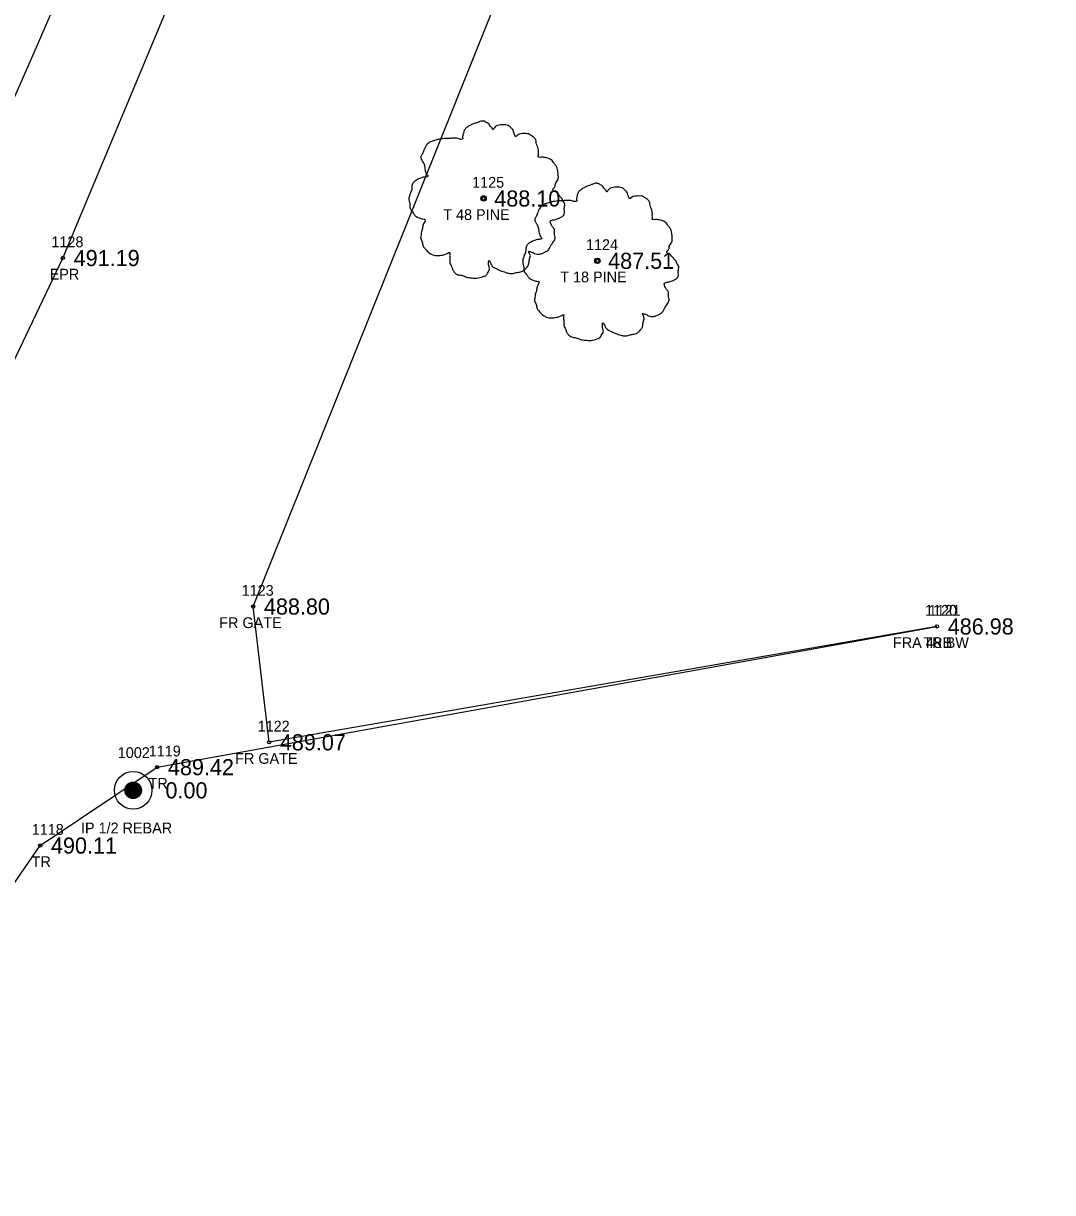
# Model space of a CAD drawing. Extents: x 1649047 to 1650429, y 896228 to 898747.
# Drawn here: x 1649848.7 to 1649944.4, y 897230.6 to 897339.2 of the extents above; entities that cross this region are included whole.
import ezdxf

# ---------------------------------------------------------------- set-up
doc = ezdxf.new("R2010")
doc.units = 0
for name, color, linetype in [('RD_EX_DV_Prop_txCode', 7, 'Continuous'), ('RD_EX_DV_PropPin', 7, 'Continuous'), ('RD_EX_Fence_Other', 7, 'Continuous'), ('RD_EX_Fence_Other_txCode', 7, 'Continuous'), ('RD_EX_Road', 7, 'Continuous'), ('RD_EX_Road_txCode', 7, 'Continuous'), ('RD_EX_TX_DV_Prop_ELEV', 7, 'Continuous'), ('RD_EX_TX_Fence_Other_ELEV', 7, 'Continuous'), ('RD_EX_TX_Road_ELEV', 7, 'Continuous'), ('RD_EX_TX_VEG_ELEV', 7, 'Continuous'), ('RD_EX_VEG', 7, 'Continuous'), ('RD_EX_VEG_txCode', 7, 'Continuous'), ('RD_HC_Cl', 7, 'Continuous'), ('RD_SMD_Locator', 7, 'Continuous')]:
    doc.layers.add(name, color=color, linetype=linetype)

msp = doc.modelspace()

# ---------------------------------------------------------------- linework, layer by layer
at = {"layer": 'RD_EX_DV_PropPin'}
for p, q in [((1649858.22, 897267.7), (1649858.22, 897268.29)), ((1649858.25, 897267.62), (1649858.25, 897268.36)), ((1649858.29, 897267.57), (1649858.29, 897268.42)), ((1649858.32, 897267.52), (1649858.32, 897268.47)), ((1649858.36, 897267.48), (1649858.36, 897268.51)), ((1649858.39, 897267.44), (1649858.39, 897268.54)), ((1649858.43, 897267.41), (1649858.43, 897268.58)), ((1649858.46, 897267.38), (1649858.46, 897268.6)), ((1649858.5, 897267.36), (1649858.5, 897268.63)), ((1649858.53, 897267.34), (1649858.53, 897268.65)), ((1649858.57, 897267.32), (1649858.57, 897268.67)), ((1649858.6, 897267.3), (1649858.6, 897268.69)), ((1649858.64, 897267.29), (1649858.64, 897268.7)), ((1649858.67, 897267.27), (1649858.67, 897268.71)), ((1649858.71, 897267.26), (1649858.71, 897268.72)), ((1649858.74, 897267.25), (1649858.74, 897268.73)), ((1649858.78, 897267.25), (1649858.78, 897268.74)), ((1649858.81, 897267.24), (1649858.81, 897268.75)), ((1649858.85, 897267.24), (1649858.85, 897268.75)), ((1649858.88, 897267.23), (1649858.88, 897268.75)), ((1649858.92, 897267.23), (1649858.92, 897268.75)), ((1649858.95, 897267.23), (1649858.95, 897268.75)), ((1649858.99, 897267.24), (1649858.99, 897268.75)), ((1649859.02, 897267.24), (1649859.02, 897268.75)), ((1649859.06, 897267.25), (1649859.06, 897268.74)), ((1649859.09, 897267.25), (1649859.09, 897268.73)), ((1649859.13, 897267.26), (1649859.13, 897268.72)), ((1649859.16, 897267.27), (1649859.16, 897268.71)), ((1649859.2, 897267.29), (1649859.2, 897268.7)), ((1649859.23, 897267.3), (1649859.23, 897268.69)), ((1649859.27, 897267.32), (1649859.27, 897268.67)), ((1649859.3, 897267.34), (1649859.3, 897268.65)), ((1649859.34, 897267.36), (1649859.34, 897268.63)), ((1649859.37, 897267.38), (1649859.37, 897268.6)), ((1649859.41, 897267.41), (1649859.41, 897268.58)), ((1649859.44, 897267.44), (1649859.44, 897268.54)), ((1649859.48, 897267.48), (1649859.48, 897268.51)), ((1649859.51, 897267.52), (1649859.51, 897268.47)), ((1649859.55, 897267.57), (1649859.55, 897268.42)), ((1649859.58, 897267.62), (1649859.58, 897268.36)), ((1649859.62, 897267.7), (1649859.62, 897268.29)), ((1649858.18, 897267.8), (1649858.18, 897268.19)), ((1649859.65, 897267.8), (1649859.65, 897268.19))]:
    msp.add_line(p, q, dxfattribs=at)
for radius in [1.75, 0.761]:
    msp.add_circle((1649858.92, 897267.99), radius, dxfattribs=at)
at = {"layer": 'RD_EX_Fence_Other'}
msp.add_lwpolyline([(1649933.62, 897283.21), (1649871.55, 897272.45), (1649870.07, 897285.06), (1649898.31, 897355.41), (1649920.55, 897411.26), (1649908.3, 897415.25)], dxfattribs=at)
at = {"layer": 'RD_EX_Road'}
msp.add_lwpolyline([(1649474.75, 896792.65), (1649502.78, 896827.35), (1649565.2, 896903.92), (1649598.28, 896943.71), (1649629.8, 896982.26), (1649667.92, 897029.33), (1649693.13, 897061.44), (1649723.58, 897101.84), (1649752.37, 897141.09), (1649779.72, 897182.3), (1649806.12, 897225.84), (1649830.13, 897270.79), (1649852.39, 897317.43), (1649871.98, 897364.35), (1649886.55, 897406.09)], dxfattribs=at)
at = {"layer": 'RD_EX_VEG'}
msp.add_lwpolyline([(1649692.17, 896958.45), (1649681.22, 896988.83), (1649682.34, 897025.02), (1649740.01, 897089.71), (1649819.17, 897217.64), (1649850.28, 897262.86), (1649861.15, 897270.14), (1649933.62, 897283.21)], dxfattribs=at)
for centre, radius in [((1649891.48, 897322.96), 0.25), ((1649891.47, 897322.94), 0.0001), ((1649902.06, 897317.17), 0.25), ((1649902.05, 897317.15), 0.0001)]:
    msp.add_circle(centre, radius, dxfattribs=at)
for points in [[(1649891.61, 897330.13), (1649891.31, 897330.15), (1649890.99, 897330.05), (1649890.74, 897329.95), (1649890.51, 897329.88), (1649890.29, 897329.78), (1649889.99, 897329.6), (1649889.76, 897329.4), (1649889.64, 897329.15), (1649889.59, 897328.93), (1649889.54, 897328.65), (1649889.54, 897328.48), (1649889.41, 897328.45), (1649889.26, 897328.48), (1649889.01, 897328.55), (1649888.76, 897328.55), (1649888.51, 897328.55), (1649888.16, 897328.53), (1649887.81, 897328.53), (1649887.54, 897328.48), (1649887.21, 897328.43), (1649886.84, 897328.3), (1649886.49, 897328.18), (1649886.19, 897327.93), (1649885.94, 897327.45), (1649885.81, 897327.1), (1649885.66, 897326.85), (1649885.81, 897326.4), (1649885.99, 897326.05), (1649886.01, 897325.85), (1649886.09, 897325.43), (1649886.19, 897325.2), (1649886.31, 897325), (1649886.24, 897324.98), (1649885.86, 897324.93), (1649885.56, 897324.83), (1649885.14, 897324.6), (1649884.91, 897324.38), (1649884.81, 897324.05), (1649884.79, 897323.7), (1649884.69, 897323.5), (1649884.61, 897323.23), (1649884.59, 897323.15), (1649884.54, 897322.83), (1649884.64, 897322.38), (1649884.66, 897322.03), (1649884.79, 897321.81), (1649884.94, 897321.63), (1649885.11, 897321.38), (1649885.51, 897321.16), (1649885.84, 897321.06), (1649886.04, 897321.03), (1649885.86, 897320.53), (1649885.81, 897320.18), (1649885.69, 897319.78), (1649885.69, 897319.71), (1649885.64, 897319.23), (1649885.79, 897318.91), (1649885.86, 897318.53), (1649886.04, 897318.31), (1649886.31, 897318.01), (1649886.64, 897317.78), (1649887.14, 897317.66), (1649887.54, 897317.68), (1649888.11, 897317.86), (1649888.36, 897317.93), (1649888.34, 897317.76), (1649888.36, 897317.38), (1649888.36, 897316.96), (1649888.51, 897316.63), (1649888.61, 897316.36), (1649888.76, 897316.11), (1649889.09, 897315.88), (1649889.49, 897315.81), (1649889.91, 897315.66), (1649890.36, 897315.58), (1649890.86, 897315.56), (1649891.46, 897315.71), (1649891.74, 897315.83), (1649891.84, 897316.01), (1649892.04, 897316.38), (1649891.99, 897316.61), (1649892.01, 897317.21), (1649892.11, 897317.03), (1649892.29, 897316.68), (1649892.78, 897316.38), (1649893.18, 897316.21), (1649893.66, 897316.06), (1649893.96, 897315.98), (1649894.43, 897316.06), (1649894.81, 897316.13), (1649895.18, 897316.26), (1649895.48, 897316.53), (1649895.66, 897316.81), (1649895.71, 897317.08), (1649895.78, 897317.46), (1649895.83, 897317.63)], [(1649895.83, 897317.63), (1649895.76, 897317.81), (1649895.71, 897318.06), (1649895.78, 897318.03), (1649895.96, 897317.98), (1649896.23, 897317.86), (1649896.46, 897317.78), (1649896.78, 897317.81), (1649897.06, 897317.91), (1649897.51, 897318.18), (1649897.78, 897318.66), (1649898.06, 897319.06), (1649898.13, 897319.38), (1649898.08, 897319.61), (1649898.06, 897320.11), (1649897.86, 897320.36), (1649897.81, 897320.48), (1649897.71, 897320.88), (1649897.78, 897320.93), (1649898.06, 897320.98), (1649898.43, 897321.11), (1649898.71, 897321.23), (1649898.93, 897321.41), (1649899.01, 897321.63), (1649898.98, 897322.03), (1649899.03, 897322.43), (1649898.96, 897322.58), (1649898.86, 897322.73), (1649898.78, 897322.93), (1649898.63, 897323.08), (1649898.53, 897323.23), (1649898.43, 897323.33), (1649898.31, 897323.48), (1649898.13, 897323.6), (1649897.98, 897323.65), (1649897.93, 897323.8), (1649898.08, 897324), (1649898.13, 897324.1), (1649898.16, 897324.33), (1649898.38, 897324.68), (1649898.43, 897325.08), (1649898.38, 897325.5), (1649898.33, 897325.78), (1649898.18, 897326.05), (1649897.98, 897326.3), (1649897.86, 897326.48), (1649897.68, 897326.6), (1649897.36, 897326.73), (1649897.11, 897326.78), (1649896.76, 897326.78), (1649896.56, 897326.83), (1649896.58, 897326.88), (1649896.58, 897327.03), (1649896.58, 897327.3), (1649896.51, 897327.75), (1649896.36, 897328.25), (1649896.36, 897328.28), (1649896.26, 897328.53), (1649896.03, 897328.73), (1649895.86, 897328.83), (1649895.66, 897328.95), (1649895.41, 897328.98), (1649895.11, 897328.98), (1649894.83, 897328.93), (1649894.63, 897328.83), (1649894.46, 897328.7), (1649894.38, 897328.85), (1649894.28, 897329.15), (1649894.23, 897329.3), (1649894.08, 897329.48), (1649893.86, 897329.68), (1649893.41, 897329.8), (1649892.78, 897329.73), (1649892.49, 897329.53), (1649892.34, 897329.35), (1649892.29, 897329.48), (1649892.09, 897329.68), (1649891.99, 897329.85), (1649891.81, 897329.98), (1649891.66, 897330.08), (1649891.56, 897330.13)], [(1649902.2, 897324.34), (1649901.9, 897324.37), (1649901.57, 897324.27), (1649901.32, 897324.17), (1649901.1, 897324.09), (1649900.87, 897323.99), (1649900.57, 897323.82), (1649900.35, 897323.62), (1649900.22, 897323.37), (1649900.17, 897323.14), (1649900.12, 897322.87), (1649900.12, 897322.69), (1649900, 897322.67), (1649899.85, 897322.69), (1649899.6, 897322.77), (1649899.35, 897322.77), (1649899.1, 897322.77), (1649898.75, 897322.74), (1649898.4, 897322.74), (1649898.12, 897322.69), (1649897.8, 897322.64), (1649897.42, 897322.52), (1649897.07, 897322.39), (1649896.77, 897322.14), (1649896.52, 897321.67), (1649896.4, 897321.32), (1649896.25, 897321.07), (1649896.4, 897320.62), (1649896.57, 897320.27), (1649896.6, 897320.07), (1649896.67, 897319.64), (1649896.77, 897319.42), (1649896.9, 897319.22), (1649896.82, 897319.19), (1649896.45, 897319.14), (1649896.15, 897319.04), (1649895.72, 897318.82), (1649895.5, 897318.59), (1649895.4, 897318.27), (1649895.37, 897317.92), (1649895.27, 897317.72), (1649895.2, 897317.44), (1649895.17, 897317.37), (1649895.12, 897317.04), (1649895.22, 897316.59), (1649895.25, 897316.24), (1649895.37, 897316.02), (1649895.52, 897315.84), (1649895.7, 897315.59), (1649896.1, 897315.37), (1649896.42, 897315.27), (1649896.62, 897315.24), (1649896.45, 897314.74), (1649896.4, 897314.4), (1649896.27, 897314), (1649896.27, 897313.92), (1649896.22, 897313.45), (1649896.37, 897313.12), (1649896.45, 897312.75), (1649896.62, 897312.52), (1649896.9, 897312.22), (1649897.22, 897312), (1649897.72, 897311.87), (1649898.12, 897311.9), (1649898.7, 897312.07), (1649898.95, 897312.15), (1649898.92, 897311.97), (1649898.95, 897311.6), (1649898.95, 897311.17), (1649899.1, 897310.85), (1649899.2, 897310.57), (1649899.35, 897310.32), (1649899.67, 897310.1), (1649900.07, 897310.02), (1649900.5, 897309.87), (1649900.95, 897309.8), (1649901.45, 897309.77), (1649902.05, 897309.92), (1649902.32, 897310.05), (1649902.42, 897310.22), (1649902.62, 897310.6), (1649902.57, 897310.82), (1649902.6, 897311.42), (1649902.7, 897311.25), (1649902.87, 897310.9), (1649903.37, 897310.6), (1649903.77, 897310.42), (1649904.25, 897310.27), (1649904.54, 897310.2), (1649905.02, 897310.27), (1649905.39, 897310.35), (1649905.77, 897310.47), (1649906.07, 897310.75), (1649906.24, 897311.02), (1649906.29, 897311.3), (1649906.37, 897311.67), (1649906.42, 897311.85)], [(1649906.42, 897311.85), (1649906.34, 897312.02), (1649906.29, 897312.27), (1649906.37, 897312.25), (1649906.54, 897312.2), (1649906.82, 897312.07), (1649907.04, 897312), (1649907.37, 897312.02), (1649907.64, 897312.12), (1649908.09, 897312.4), (1649908.37, 897312.87), (1649908.64, 897313.27), (1649908.72, 897313.6), (1649908.67, 897313.82), (1649908.64, 897314.32), (1649908.44, 897314.57), (1649908.39, 897314.69), (1649908.29, 897315.09), (1649908.37, 897315.14), (1649908.64, 897315.19), (1649909.02, 897315.32), (1649909.29, 897315.44), (1649909.52, 897315.62), (1649909.59, 897315.84), (1649909.57, 897316.24), (1649909.62, 897316.64), (1649909.54, 897316.79), (1649909.44, 897316.94), (1649909.37, 897317.14), (1649909.22, 897317.29), (1649909.12, 897317.44), (1649909.02, 897317.54), (1649908.89, 897317.69), (1649908.72, 897317.82), (1649908.57, 897317.87), (1649908.52, 897318.02), (1649908.67, 897318.22), (1649908.72, 897318.32), (1649908.74, 897318.54), (1649908.97, 897318.89), (1649909.02, 897319.29), (1649908.97, 897319.72), (1649908.92, 897319.99), (1649908.77, 897320.27), (1649908.57, 897320.52), (1649908.44, 897320.69), (1649908.27, 897320.82), (1649907.94, 897320.94), (1649907.69, 897320.99), (1649907.34, 897320.99), (1649907.14, 897321.04), (1649907.17, 897321.09), (1649907.17, 897321.24), (1649907.17, 897321.52), (1649907.09, 897321.97), (1649906.94, 897322.47), (1649906.94, 897322.49), (1649906.84, 897322.74), (1649906.62, 897322.94), (1649906.44, 897323.04), (1649906.24, 897323.17), (1649905.99, 897323.19), (1649905.69, 897323.19), (1649905.42, 897323.14), (1649905.22, 897323.04), (1649905.04, 897322.92), (1649904.97, 897323.07), (1649904.87, 897323.37), (1649904.82, 897323.52), (1649904.67, 897323.69), (1649904.45, 897323.89), (1649904, 897324.02), (1649903.37, 897323.94), (1649903.07, 897323.74), (1649902.92, 897323.57), (1649902.87, 897323.69), (1649902.67, 897323.89), (1649902.57, 897324.07), (1649902.4, 897324.19), (1649902.25, 897324.29), (1649902.15, 897324.34)]]:
    msp.add_spline(points, degree=3, dxfattribs=at)
at = {"layer": 'RD_HC_Cl'}
msp.add_arc((1648799.37, 897792.37), 1145, 320.82481, 10.99954, dxfattribs=at)
at = {"layer": 'RD_SMD_Locator'}
for centre in [(1649891.48, 897322.96), (1649852.39, 897317.43), (1649902.06, 897317.17), (1649870.07, 897285.06), (1649933.62, 897283.21), (1649933.62, 897283.21), (1649871.55, 897272.45), (1649861.15, 897270.14), (1649858.92, 897267.99), (1649850.28, 897262.86)]:
    msp.add_circle(centre, 0.15, dxfattribs=at)

# ---------------------------------------------------------------- texts
at = {"layer": 'RD_EX_DV_Prop_txCode'}
for s, p in [('1002', (1649857.49, 897270.99)), ('IP 1/2 REBAR', (1649854.07, 897263.99))]:
    msp.add_text(s, height=1, dxfattribs=at).set_placement(p)
at = {"layer": 'RD_EX_Fence_Other_txCode'}
for s, p in [('1123', (1649869, 897286.06)), ('1120', (1649932.51, 897284.21)), ('FR GATE', (1649866.92, 897283.06)), ('FRA 48 BW', (1649929.53, 897281.21)), ('1122', (1649870.49, 897273.45)), ('FR GATE', (1649868.4, 897270.45))]:
    msp.add_text(s, height=1, dxfattribs=at).set_placement(p)
at = {"layer": 'RD_EX_Road_txCode'}
for s, p in [('1128', (1649851.32, 897318.43)), ('EPR', (1649851.16, 897315.43))]:
    msp.add_text(s, height=1, dxfattribs=at).set_placement(p)
at = {"layer": 'RD_EX_TX_DV_Prop_ELEV'}
msp.add_text('0.00', height=1.5, dxfattribs=at).set_placement((1649861.92, 897267.24))
at = {"layer": 'RD_EX_TX_Fence_Other_ELEV'}
for s, p in [('488.80', (1649871.07, 897284.31)), ('486.98', (1649934.62, 897282.46)), ('489.07', (1649872.55, 897271.7))]:
    msp.add_text(s, height=1.5, dxfattribs=at).set_placement(p)
at = {"layer": 'RD_EX_TX_Road_ELEV'}
msp.add_text('491.19', height=1.5, dxfattribs=at).set_placement((1649853.39, 897316.68))
at = {"layer": 'RD_EX_TX_VEG_ELEV'}
for s, p in [('488.10', (1649892.48, 897322.21)), ('487.51', (1649903.06, 897316.42)), ('486.98', (1649934.62, 897282.46)), ('489.42', (1649862.15, 897269.39)), ('490.11', (1649851.28, 897262.11))]:
    msp.add_text(s, height=1.5, dxfattribs=at).set_placement(p)
at = {"layer": 'RD_EX_VEG_txCode'}
for s, p in [('1125', (1649890.42, 897323.96)), ('T 48 PINE', (1649887.74, 897320.96)), ('1124', (1649901, 897318.17)), ('T 18 PINE', (1649898.61, 897315.17)), ('1121', (1649932.84, 897284.21)), ('TRB', (1649932.35, 897281.21)), ('1119', (1649860.37, 897271.14)), ('TR', (1649860.35, 897268.14)), ('1118', (1649849.5, 897263.86)), ('TR', (1649849.49, 897260.86))]:
    msp.add_text(s, height=1, dxfattribs=at).set_placement(p)

doc.saveas('drawing.dxf')
